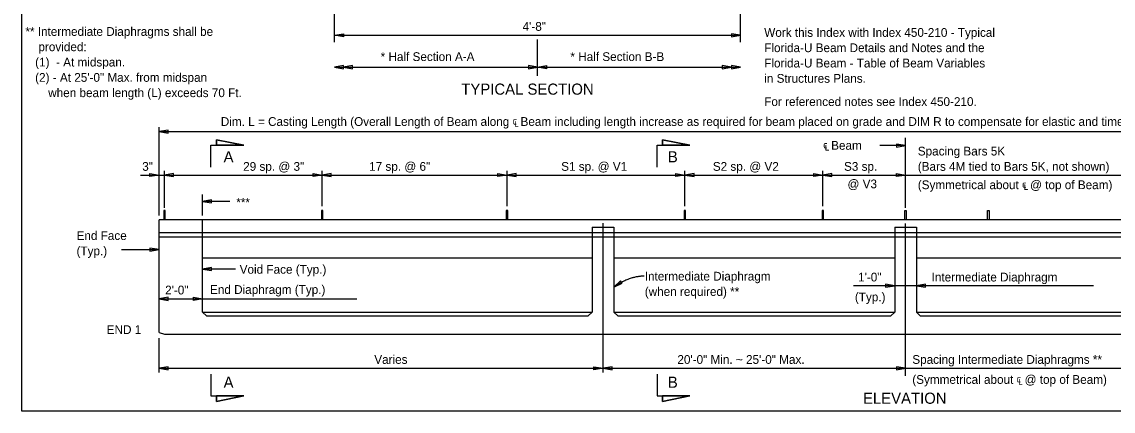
# Model space of a CAD drawing. Extents: x 0 to 20.5, y 0 to 12.9.
# Drawn here: x 0 to 12.54, y 0 to 4.48 of the extents above; entities that cross this region are included whole.
import ezdxf

# ---------------------------------------------------------------- set-up
doc = ezdxf.new("R2010")
doc.units = 0
for name, color, linetype in [('ActivePts-ConstElements', 7, 'Continuous'), ('BeamConc', 7, 'Continuous'), ('BeamConc_h', 7, 'Continuous'), ('CL_Major', 7, 'Continuous'), ('Dimension', 7, 'Continuous'), ('Rebar', 7, 'Continuous'), ('TextStructures', 7, 'Continuous')]:
    doc.layers.add(name, color=color, linetype=linetype)

# ---------------------------------------------------------------- blocks, each defined once
blk = doc.blocks.new('ALT')
at = {"layer": 'Dimension'}
for points in [[(0, 0), (-0.00041, -0.000069), (-0.00041, 0.000069)], [(-0.000121, 0), (-0.000397, -0.000043), (-0.000397, 0.000043)], [(-0.000233, 0), (-0.000374, -0.000023), (-0.000374, 0.000023)]]:
    blk.add_lwpolyline(points, close=True, dxfattribs=at)

msp = doc.modelspace()

# ---------------------------------------------------------------- linework, layer by layer
at = {"layer": 'ActivePts-ConstElements'}
msp.add_lwpolyline([(0, 12.947), (20.485, 12.947), (20.485, 0), (0, 0)], close=True, dxfattribs=at)
at = {"layer": 'BeamConc'}
for p, q in [((1.577, 0.903), (1.577, 2.199)), ((19.112, 2.199), (1.577, 2.199)), ((1.577, 2.054), (19.112, 2.054)), ((1.577, 2.004), (19.112, 2.004)), ((1.577, 0.903), (1.639, 0.887)), ((1.639, 0.887), (19.05, 0.887))]:
    msp.add_line(p, q, dxfattribs=at)
at = {"layer": 'BeamConc_h'}
for p, q in [((2.077, 1.139), (2.077, 2.199)), ((6.555, 2.116), (6.805, 2.116)), ((6.555, 2.116), (6.555, 1.139)), ((6.805, 2.116), (6.805, 1.139)), ((10.033, 2.116), (10.283, 2.116)), ((10.033, 2.116), (10.033, 1.139)), ((10.283, 2.116), (10.283, 1.139)), ((2.077, 1.762), (6.555, 1.762)), ((6.805, 1.762), (10.033, 1.762)), ((10.283, 1.762), (13.51, 1.762)), ((2.121, 1.095), (2.077, 1.139)), ((2.077, 1.139), (6.555, 1.139)), ((6.511, 1.095), (6.555, 1.139)), ((6.805, 1.139), (10.033, 1.139)), ((6.85, 1.095), (6.805, 1.139)), ((9.988, 1.095), (10.033, 1.139)), ((10.283, 1.139), (13.51, 1.139)), ((10.327, 1.095), (10.283, 1.139)), ((2.121, 1.095), (6.511, 1.095)), ((6.85, 1.095), (9.988, 1.095)), ((10.327, 1.095), (13.465, 1.095))]:
    msp.add_line(p, q, dxfattribs=at)
at = {"layer": 'CL_Major'}
for p, q in [((5.926, 3.853), (5.926, 4.272)), ((10.158, 2.339), (10.158, 3.143)), ((6.68, 0.446), (6.68, 2.162)), ((10.158, 0.406), (10.158, 2.156))]:
    msp.add_line(p, q, dxfattribs=at)
at = {"layer": 'Dimension'}
for p, q in [((3.593, 4.241), (3.593, 4.598)), ((8.26, 4.241), (8.26, 4.598)), ((3.593, 4.321), (8.26, 4.321)), ((3.593, 3.955), (8.26, 3.955)), ((1.577, 2.25), (1.577, 3.264)), ((1.577, 3.213), (19.112, 3.213)), ((2.174, 2.805), (2.174, 3.056)), ((2.174, 3.056), (2.55, 3.056)), ((2.55, 3.056), (2.236, 3.119)), ((2.236, 3.119), (2.236, 3.056)), ((7.302, 2.805), (7.302, 3.056)), ((7.302, 3.056), (7.679, 3.056)), ((7.679, 3.056), (7.365, 3.119)), ((7.365, 3.119), (7.365, 3.056)), ((10.158, 3.054), (9.86, 3.054)), ((1.639, 2.337), (1.639, 2.764)), ((3.452, 2.357), (3.452, 2.764)), ((5.577, 2.357), (5.577, 2.764)), ((7.622, 2.357), (7.622, 2.764)), ((9.207, 2.357), (9.207, 2.764)), ((1.363, 2.713), (13.376, 2.713)), ((2.077, 2.25), (2.077, 2.491)), ((2.39, 2.41), (2.077, 2.41)), ((1.144, 1.858), (1.577, 1.858)), ((2.457, 1.633), (2.077, 1.633)), ((12.318, 1.441), (9.561, 1.441)), ((1.577, 1.292), (3.849, 1.292)), ((1.577, 0.446), (1.577, 0.839)), ((1.577, 0.493), (13.244, 0.493)), ((2.174, 0.426), (2.174, 0.175)), ((7.302, 0.426), (7.302, 0.175)), ((2.174, 0.175), (2.55, 0.175)), ((2.55, 0.175), (2.236, 0.112)), ((2.236, 0.112), (2.236, 0.175)), ((7.302, 0.175), (7.679, 0.175)), ((7.679, 0.175), (7.365, 0.112)), ((7.365, 0.112), (7.365, 0.175))]:
    msp.add_line(p, q, dxfattribs=at)
for points in [[(8.26, 4.321), (8.156, 4.339), (8.156, 4.304)], [(3.593, 3.955), (3.697, 3.937), (3.697, 3.973)], [(3.697, 3.955), (3.801, 3.937), (3.801, 3.973)], [(5.926, 3.955), (5.822, 3.973), (5.822, 3.937)], [(5.926, 3.955), (6.03, 3.973), (6.03, 3.937)], [(8.156, 3.955), (8.051, 3.973), (8.051, 3.937)], [(8.26, 3.955), (8.156, 3.973), (8.156, 3.937)], [(1.577, 3.213), (1.681, 3.196), (1.681, 3.231)], [(2.236, 3.056), (2.236, 3.119), (2.55, 3.056)], [(7.365, 3.056), (7.365, 3.119), (7.679, 3.056)], [(10.158, 3.054), (10.053, 3.071), (10.053, 3.036)], [(1.577, 2.713), (1.473, 2.696), (1.473, 2.731)], [(1.639, 2.713), (1.744, 2.696), (1.744, 2.731)], [(3.452, 2.713), (3.348, 2.696), (3.348, 2.731)], [(3.452, 2.713), (3.556, 2.696), (3.556, 2.731)], [(5.577, 2.713), (5.473, 2.696), (5.473, 2.731)], [(5.577, 2.713), (5.681, 2.696), (5.681, 2.731)], [(7.622, 2.713), (7.517, 2.696), (7.517, 2.731)], [(7.622, 2.713), (7.726, 2.696), (7.726, 2.731)], [(9.206, 2.713), (9.102, 2.696), (9.102, 2.731)], [(9.206, 2.713), (9.311, 2.696), (9.311, 2.731)], [(10.157, 2.713), (10.053, 2.696), (10.053, 2.731)], [(2.077, 2.41), (2.181, 2.393), (2.181, 2.428)], [(1.577, 1.858), (1.473, 1.875), (1.473, 1.84)], [(2.077, 1.633), (2.181, 1.616), (2.181, 1.651)], [(6.806, 1.425), (6.901, 1.471), (6.881, 1.5)], [(10.033, 1.441), (9.928, 1.459), (9.928, 1.424)], [(10.283, 1.441), (10.387, 1.424), (10.387, 1.459)], [(1.577, 1.292), (1.681, 1.274), (1.681, 1.309)], [(2.077, 1.292), (1.973, 1.274), (1.973, 1.309)], [(1.577, 0.493), (1.681, 0.476), (1.681, 0.511)], [(6.68, 0.493), (6.576, 0.476), (6.576, 0.511)], [(6.68, 0.493), (6.785, 0.476), (6.785, 0.511)], [(10.158, 0.493), (10.053, 0.511), (10.053, 0.476)], [(2.236, 0.175), (2.236, 0.112), (2.55, 0.175)], [(7.365, 0.175), (7.365, 0.112), (7.679, 0.175)]]:
    msp.add_lwpolyline(points, close=True, dxfattribs=at)
msp.add_open_spline([(7.153, 1.552), (6.984, 1.552), (6.806, 1.425)], degree=2, dxfattribs=at)
at = {"layer": 'Rebar'}
for p, q in [((1.648, 2.307), (1.631, 2.307)), ((1.631, 2.307), (1.631, 2.2)), ((1.648, 2.2), (1.648, 2.307)), ((3.461, 2.307), (3.443, 2.307)), ((3.443, 2.307), (3.443, 2.2)), ((3.461, 2.2), (3.461, 2.307)), ((5.586, 2.307), (5.568, 2.307)), ((5.568, 2.307), (5.568, 2.2)), ((5.586, 2.2), (5.586, 2.307)), ((7.63, 2.307), (7.613, 2.307)), ((7.613, 2.307), (7.613, 2.2)), ((7.63, 2.2), (7.63, 2.307)), ((9.215, 2.307), (9.198, 2.307)), ((9.198, 2.307), (9.198, 2.2)), ((9.215, 2.2), (9.215, 2.307)), ((10.149, 2.2), (10.149, 2.307)), ((10.149, 2.307), (10.166, 2.307)), ((10.166, 2.307), (10.166, 2.2)), ((11.1, 2.2), (11.1, 2.307)), ((11.1, 2.307), (11.117, 2.307)), ((11.117, 2.307), (11.117, 2.2))]:
    msp.add_line(p, q, dxfattribs=at)

# ---------------------------------------------------------------- block references
at = {"layer": 'Dimension', "xscale": 254, "yscale": 255.88988095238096, "rotation": 180}
msp.add_blockref('ALT', (3.593, 4.321), dxfattribs=at)
msp.add_blockref('ALT', (3.593, 4.321), dxfattribs=at)
at = {"layer": 'Dimension', "xscale": 164.50777202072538, "yscale": 167.927734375}
msp.add_blockref('ALT', (10.158, 2.713), dxfattribs=at)
msp.add_blockref('ALT', (10.158, 2.713), dxfattribs=at)

# ---------------------------------------------------------------- texts
at = {"layer": 'Dimension'}
for s, p in [('** Intermediate Diaphragms shall be', (0.041, 4.314)), ('  Work this Index with Index 450-210 - Typical', (8.458, 4.303)), ('    provided:', (0.041, 4.138)), ('  Florida-U Beam Details and Notes and the', (8.458, 4.127)), ('   (1)  - At midspan.', (0.041, 3.962)), ('  Florida-U Beam - Table of Beam Variables', (8.458, 3.951)), ('   (2) - At 25\'-0" Max. from midspan', (0.041, 3.786)), ('  in Structures Plans.', (8.458, 3.775)), ('       when beam length (L) exceeds 70 Ft.', (0.041, 3.61)), ('Spacing Bars 5K', (10.298, 2.939)), ('(Bars 4M tied to Bars 5K, not shown)', (10.298, 2.763)), ('End Face', (0.629, 1.968)), ('(Typ.)', (0.629, 1.792)), ('Intermediate Diaphragm ', (7.16, 1.501)), ('(when required) **', (7.16, 1.325))]:
    msp.add_text(s, height=0.1008, dxfattribs=at).set_placement(p)
at = {"layer": 'TextStructures'}
for s, height, p in [('4\'-8"', 0.1008, (5.756, 4.372)), ('* Half Section A-A', 0.1008, (4.124, 4.025)), ('* Half Section B-B', 0.1008, (6.305, 4.025)), ('TYPICAL SECTION', 0.128, (5.051, 3.638)), ('  For referenced notes see Index 450-210.', 0.1008, (8.458, 3.508)), ('Dim. L = Casting Length (Overall Length of Beam along ℄ Beam including length increase as required for beam placed on grade and DIM R to compensate for elastic and time dependent shortening effects)', 0.1008, (2.287, 3.279)), ('℄ Beam', 0.1008, (9.21, 3.005)), ('A', 0.128, (2.319, 2.86)), ('B', 0.128, (7.425, 2.86)), ('3"', 0.1008, (1.384, 2.763)), ('29 sp. @ 3"', 0.1008, (2.544, 2.763)), ('17 sp. @ 6"', 0.1008, (3.992, 2.763)), ('S1 sp. @ V1', 0.1008, (6.199, 2.763)), ('S2 sp. @ V2', 0.1008, (7.942, 2.763)), ('S3 sp.', 0.1008, (9.45, 2.763)), ('@ V3', 0.1008, (9.49, 2.562)), ('(Symmetrical about ℄ @ top of Beam)', 0.1008, (10.298, 2.552)), ('***', 0.1008, (2.465, 2.35)), ('Void Face (Typ.)', 0.1008, (2.504, 1.58)), ('1\'-0"', 0.1008, (9.612, 1.491)), ('Intermediate Diaphragm ', 0.1008, (10.457, 1.491)), ('2\'-0"', 0.1008, (1.647, 1.342)), ('End Diaphragm (Typ.)', 0.1008, (2.163, 1.348)), ('(Typ.)', 0.1008, (9.575, 1.263)), ('END 1', 0.1008, (0.976, 0.887)), ('Varies ', 0.1008, (4.051, 0.544)), ('20\'-0" Min. ~ 25\'-0" Max. ', 0.1008, (7.535, 0.544)), ('Spacing Intermediate Diaphragms **', 0.1008, (10.235, 0.544)), ('A', 0.128, (2.319, 0.269)), ('B', 0.128, (7.425, 0.269)), ('(Symmetrical about ℄ @ top of Beam)', 0.1008, (10.235, 0.314)), ('ELEVATION', 0.128, (9.668, 0.085))]:
    msp.add_text(s, height=height, dxfattribs=at).set_placement(p)

doc.saveas('drawing.dxf')
